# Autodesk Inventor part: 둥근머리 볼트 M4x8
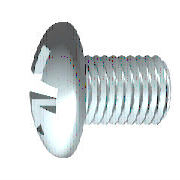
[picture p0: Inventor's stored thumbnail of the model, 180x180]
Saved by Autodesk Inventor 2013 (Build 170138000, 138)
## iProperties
Created: 2012-02
Part Number: 둥근머리 볼트 M4x8
Material: 강철, 연강
Description: 십자 오목 머리 나사
Document SubType Name: Modeling
Standard: KS B 1023
Designer: mduedu
Standards Organization: KS
Language: ko-KR
Size Designation: A  M 4 x 8 - H
Categories: <MemberInstance><Categories><Category DisplayName="조임쇠" InternalName="e4da775c-781d-43d5-af7c-5136215cf5a6" Mnemonic="FSTN"><Category DisplayName="볼트" InternalN
Density: 7.86 g/cm^3
Mass: 1.61931 g
Surface Area: 2.62079 cm^2
Volume: 0.206019 cm^3
IsCustomPart: 1
Author: mduedu
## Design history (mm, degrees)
body "Solid1"
workplane "Work Plane3"
sketch "스케치2"
  geometry: L1 (-5.374, 0)-(5.374, 0) reference; L2 (0, -5.374)-(0, 5.374) reference; L3 (0, 2.3)-(0, 0); L4 (0, 0)-(2.3, 0); L5 (0, 0)-(2.714, 2.714); L6 (0.311, 2.279)-(0.392, 0.703); L7 (2.279, 0.311)-(0.703, 0.392); L8 (0.311, -2.279)-(0.392, -0.703); L9 (2.279, -0.311)-(0.703, -0.392); L10 (-0.311, 2.279)-(-0.392, 0.703); L11 (-2.279, 0.311)-(-0.703, 0.392); L12 (-2.279, -0.311)-(-0.703, -0.392); L13 (-0.311, -2.279)-(-0.392, -0.703); A1 r 0.69 centre (0, 0) between (0.69, 0) and (0, 0.69); A2 r 2.3 centre (0, 0) between (2.3, 0) and (2.279, 0.311); A3 r 2.3 centre (0, 0) between (0.311, 2.279) and (0, 2.3); A4 r 2.3 centre (0, 0) between (2.279, 0.311) and (0.311, 2.279); A5 r 2.3 centre (0, 0) between (0, -2.3) and (0.311, -2.279); A6 r 2.3 centre (0, 0) between (0.311, -2.279) and (2.279, -0.311); A7 r 2.3 centre (0, 0) between (2.279, -0.311) and (2.3, 0); A8 r 2.3 centre (0, 0) between (-2.279, 0.311) and (-2.3, 0); A9 r 2.3 centre (0, 0) between (-0.311, 2.279) and (-2.279, 0.311); A10 r 2.3 centre (0, 0) between (0, 2.3) and (-0.311, 2.279); A11 r 2.3 centre (0, 0) between (-2.3, 0) and (-2.279, -0.311); A12 r 2.3 centre (0, 0) between (-2.279, -0.311) and (-0.311, -2.279); A13 r 2.3 centre (0, 0) between (-0.311, -2.279) and (0, -2.3); A14 r 0.805 centre (0, 0) between (0.805, 0) and (0, 0.805); A15 r 0.328 centre (0.72, 0.72) between (0.392, 0.703) and (0.703, 0.392); A16 r 0.328 centre (0.72, -0.72) between (0.703, -0.392) and (0.392, -0.703); A17 r 0.328 centre (-0.72, 0.72) between (-0.703, 0.392) and (-0.392, 0.703); A18 r 0.328 centre (-0.72, -0.72) between (-0.392, -0.703) and (-0.703, -0.392); 1 further point
  constraints: 38 point on circle, 22 end point, 19 symmetric about line, 18 centre point, 4 coincident, 3 collinear, 3 point on line, 3 tangent, 1 perpendicular, 21 other
  dimensions: "d4" = 45 deg angle of L5 L4; "d5" = 1.38 diameter of A1 (= 0.3 x SDM); "d6" = 4.6 diameter of A4 (= SDM); "d7" = 0.3115 distance from line of L6.start L3 (= 0.5 x SBR); "d14" = 1.61 diameter of A14 (= 0.35 x SDM)
extrude "슬롯" join sketch "스케치2" taper "d15" = 5 deg; stored distance "d54" = 10
revolve "절단부" stored, may be unused: angle "d56" = 90 deg
revolve "본체" stored, may be unused: angle "d18" = 90 deg
workplane "Work Plane1"
sketch "스케치1"
  geometry: L1 (8, 0)-(8, 2); L2 (8, 2)-(1.4, 2); L3 (3.962, 5.08)-(3.962, 5.08); L4 (-3.1, 0)-(-3.1, 3.729); L5 (-2.744, 2.122)-(-1.498, 1.501); L6 (-1.498, 1.501)-(-0.7, 0); L7 (-0.7, 0)-(8, 0); L8 (-5.687, 0)-(10.281, 0) reference; L9 (0, -1.016)-(0, 6.096) reference; L10 (-2.744, 2.122)-(-3.1, 2.3); L11 (-1.846, 3.839)-(-3.1, 3.729); L12 (-1.846, 3.839)-(0, 4); L13 (0, 4)-(0, 1.785); L14 (0, 1.785)-(0.971, 1.785); L15 (0.971, 1.785)-(1.4, 2); L16 (1.4, 2)-(0, 2); A1 r 6.5 centre (3.4, 0) between (-1.846, 3.839) and (-3.1, 0)
  constraints: 28 end point, 5 point on line, 4 collinear, 4 point on circle, 3 parallel, 2 perpendicular, 1 centre point, 1 horizontal, 1 tangent
  dimensions: "d1" = 4 diameter of L2 L7 (= GD); "d2" = 2.4 distance from line of L6.end L4 (= STI); "d11" = 4.6 diameter of L10.end L7 (= SDM); "d12" = 62 deg angle of L6 L7; "d13" = 26.5 deg angle of L5 L7; "d17" = 8 diameter of L12.end L7 (= KOD); "d19" = 5 deg angle of L12 L7 (= KEWI); "d20" = 3.1 distance between parallel lines of L4 L13 (= KOH); "d21" = 6.5 radius of A1 (= KR); "d23" = 3.5705 diameter of L14 L7 (= BDM); "d24" = 6.6 distance of L1.end L2.end (= GEL); "d25" = 0.42941 horizontal distance of L14.end L2.end (= GAL); "d28" = 8 distance between parallel lines of L1 L13 (= NLG)
fillet "모깎기1" dims "d29" = 1.6 (= RR)
fillet "모깎기2" dims "d16" = 0.1246 (= 0.2 x SBR)
feature "스레드" dims "d8" = 6.6 (= GEL), "d9" = 0
chamfer "모따기1" distance "d26" = 0.42941 (= -0.5 x SPD + 0.5 x GD); stored, may be unused: second distance "d27" = 0.42952 (computed from GUL), angle "d78" = 45 deg
other parameters: "GD" = 4 (= NND) [user parameter; used in 2 equation terms], "NLG" = 8 [user parameter; used in 1 equation term], "GEL" = 6.6 [user parameter; used in 2 equation terms], "KOD" = 8 [user parameter; used in 1 equation term], "KOH" = 3.1 [user parameter; used in 2 equation terms], "SDM" = 4.6 [user parameter; used in 4 equation terms], "STI" = 2.4 [user parameter; used in 1 equation term], "SBR" = 0.623 [user parameter; used in 2 equation terms], "GAL" = 0.42941 (= 0.61345 x PTC) [user parameter; used in 1 equation term], "SPD" = 3.14117 (= NND - 1.2269 x PTC) [user parameter; used in 1 equation term], "KEWI" = 5 deg [user parameter; used in 1 equation term], "d3" = -3.1 (= -KOH), "d10" = 0, "KR" = 6.5 [user parameter; used in 1 equation term], "BDM" = 3.5705 [user parameter; used in 1 equation term], "GUL" = 0.42941 (= 0.61345 x PTC) [user parameter; used in 1 equation term], "RR" = 1.6 [user parameter; used in 1 equation term], "d79" = 0, "d80" = 0, "PTC" = 0.7 [user parameter; used in 5 equation terms], "THREADDIA" = 4 [user parameter; used in 1 equation term], "TOA" = 30 deg [user parameter], "TPU" = 14.28571 (computed from PTC) [user parameter], "NND" = 4 [user parameter; used in 2 equation terms], "GD1" = 3.14117 (= THREADDIA - 1.2269 x PTC) [user parameter]
